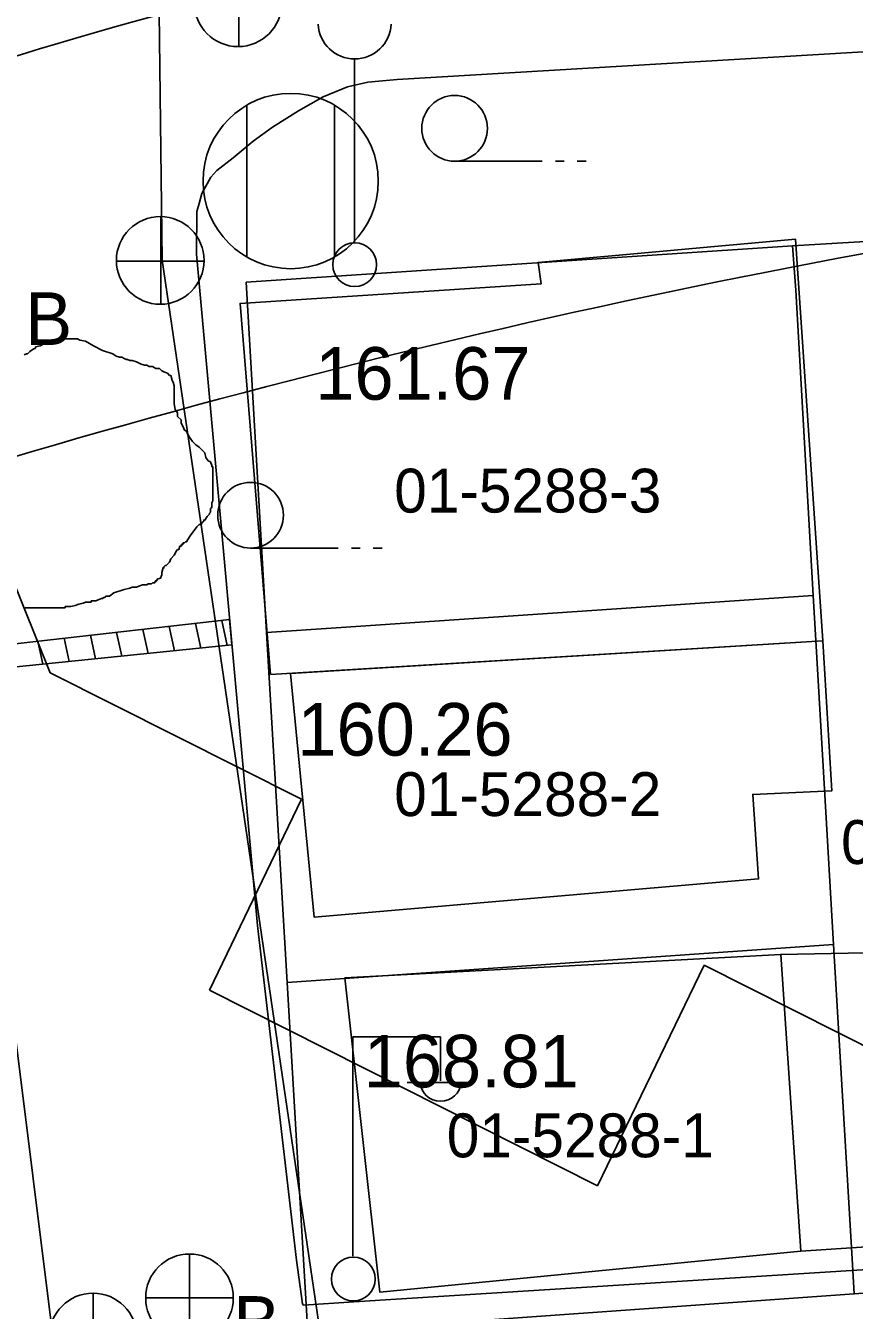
# Model space of a CAD drawing. Extents: x 419101 to 420177, y 4451541 to 4452254.
# Drawn here: x 419848.32 to 419867.23, y 4451802.86 to 4451832.16 of the extents above; entities that cross this region are included whole.
import ezdxf

# ---------------------------------------------------------------- set-up
doc = ezdxf.new("R2010")
doc.units = 0
for name, color, linetype in [('2_KADASTRO', 7, 'Continuous'), ('3_HALİHAZIR', 7, 'Continuous'), ('Level 10', 7, 'Continuous'), ('Level 3', 7, 'Continuous'), ('Level 60', 7, 'Continuous'), ('Level 62', 7, 'Continuous')]:
    doc.layers.add(name, color=color, linetype=linetype)

msp = doc.modelspace()

# ---------------------------------------------------------------- linework, layer by layer
at = {"layer": '2_KADASTRO'}
for points in [[(419865.822, 4451827.135), (419867.101, 4451827.211), (419873.808, 4451827.609), (419874.764, 4451812.159), (419875.281, 4451803.805), (419867.231, 4451803.234), (419867.184, 4451804.033), (419866.761, 4451811.2), (419866.552, 4451814.744), (419866.352, 4451818.137), (419866.293, 4451819.166), (419865.895, 4451826.126)], [(419853.349, 4451826.308), (419865.822, 4451827.135), (419865.895, 4451826.126), (419866.293, 4451819.166), (419855.404, 4451818.429), (419853.82, 4451818.321)], [(419853.82, 4451818.321), (419855.404, 4451818.429), (419866.293, 4451819.166), (419866.352, 4451818.137), (419866.552, 4451814.744), (419866.761, 4451811.2), (419864.238, 4451811.025), (419856.147, 4451810.464), (419854.291, 4451810.335)], [(419854.291, 4451810.335), (419856.147, 4451810.464), (419864.238, 4451811.025), (419866.761, 4451811.2), (419867.184, 4451804.033), (419867.231, 4451803.234), (419854.762, 4451802.349)]]:
    msp.add_lwpolyline(points, close=True, dxfattribs=at)
at = {"layer": '3_HALİHAZIR'}
for p, q in [((419853.184, 4451831.675), (419853.184, 4451833.675)), ((419855.828, 4451827.209), (419855.828, 4451831.402)), ((419853.368, 4451826.886), (419853.368, 4451830.346)), ((419855.368, 4451826.886), (419855.368, 4451830.346)), ((419858.11, 4451829.068), (419860.11, 4451829.068)), ((419860.41, 4451829.068), (419860.61, 4451829.068)), ((419860.91, 4451829.068), (419861.11, 4451829.068)), ((419851.406, 4451825.798), (419851.406, 4451827.798)), ((419850.386, 4451826.788), (419852.386, 4451826.788)), ((419853.453, 4451820.244), (419855.453, 4451820.244)), ((419855.753, 4451820.244), (419855.953, 4451820.244)), ((419856.253, 4451820.244), (419856.453, 4451820.244)), ((419850.995, 4451818.391), (419851.117, 4451817.841)), ((419851.594, 4451818.459), (419851.718, 4451817.903)), ((419852.194, 4451818.527), (419852.319, 4451817.965)), ((419852.794, 4451818.595), (419852.92, 4451818.026)), ((419848.597, 4451818.119), (419848.713, 4451817.595)), ((419849.196, 4451818.187), (419849.314, 4451817.657)), ((419849.796, 4451818.255), (419849.915, 4451817.718)), ((419850.395, 4451818.323), (419850.516, 4451817.78)), ((419855.79, 4451804.097), (419855.79, 4451809.097)), ((419855.79, 4451809.097), (419857.79, 4451809.097)), ((419857.79, 4451808.097), (419857.79, 4451809.097)), ((419857.03, 4451808.057), (419858.53, 4451808.057)), ((419852.059, 4451804.144), (419852.059, 4451802.144)), ((419849.857, 4451803.25), (419849.857, 4451801.25)), ((419851.059, 4451803.144), (419853.059, 4451803.144))]:
    msp.add_line(p, q, dxfattribs=at)
for points in [[(419883.249, 4451832.652), (419868.981, 4451831.651), (419856.797, 4451830.93), (419856.127, 4451830.87), (419855.662, 4451830.764), (419855.112, 4451830.539), (419854.549, 4451830.22), (419853.951, 4451829.847), (419853.514, 4451829.523), (419853.056, 4451829.143), (419852.682, 4451828.854), (419852.544, 4451828.705), (419852.34, 4451828.329), (419852.279, 4451828.101), (419852.229, 4451827.92), (419852.216, 4451826.947)], [(419852.216, 4451826.947), (419853.61, 4451811.636), (419854.5, 4451804)], [(419847.624, 4451812.746), (419850.189, 4451792.286), (419852.538, 4451774.604), (419854.108, 4451764.505)], [(419884.682, 4451804.733), (419875.752, 4451804.31), (419855.808, 4451803.057), (419854.663, 4451802.975), (419854.663, 4451802.975), (419854.636, 4451803.009), (419854.5, 4451804)]]:
    msp.add_lwpolyline(points, dxfattribs=at)
for points in [[(419853.907, 4451817.359), (419853.212, 4451825.827), (419860.085, 4451826.269), (419860.016, 4451826.756), (419865.888, 4451827.293), (419866.516, 4451818.127)], [(419846.911, 4451817.411), (419846.799, 4451817.915), (419852.975, 4451818.615), (419853.027, 4451818.037)], [(419866.516, 4451818.127), (419866.723, 4451814.71), (419864.915, 4451814.625), (419865.049, 4451812.701), (419854.907, 4451811.825), (419854.362, 4451817.387)], [(419866.012, 4451804.212), (419868.664, 4451804.382), (419868.238, 4451811.029), (419865.553, 4451810.977), (419855.604, 4451810.44), (419856.402, 4451803.274)], [(419866.012, 4451804.212), (419865.553, 4451810.977), (419868.238, 4451811.029), (419868.664, 4451804.382)]]:
    msp.add_lwpolyline(points, close=True, dxfattribs=at)
for centre, radius in [((419853.168, 4451832.683), 1), ((419854.368, 4451828.616), 2), ((419858.11, 4451829.818), 0.75), ((419851.391, 4451826.806), 1), ((419855.828, 4451826.709), 0.5), ((419853.453, 4451820.994), 0.75), ((419852.059, 4451803.144), 1), ((419855.8, 4451803.573), 0.5), ((419849.857, 4451802.25), 1)]:
    msp.add_circle(centre, radius, dxfattribs=at)
for centre, radius, start, end in [((419855.828, 4451832.239), 0.837, 183.298, 356.9072), ((419857.79, 4451808.101), 0.474, 184.8384, 355.1464)]:
    msp.add_arc(centre, radius, start, end, dxfattribs=at)
at = {"layer": 'Level 10'}
msp.add_lwpolyline([(419958.201, 4451879.006), (419966.53, 4451769.671), (419931.06, 4451766.859), (419938.096, 4451697.79), (419879.097, 4451703.767), (419870.357, 4451698.446), (419851.433, 4451826.814), (419850.731, 4451885.176)], dxfattribs=at)
at = {"layer": 'Level 3'}
for points in [[(419848.285, 4451824.65), (419848.337, 4451824.676), (419848.363, 4451824.676), (419848.414, 4451824.728), (419848.492, 4451824.78), (419848.544, 4451824.806), (419848.544, 4451824.832), (419848.648, 4451824.858)], [(419848.648, 4451824.858), (419848.752, 4451824.91), (419848.855, 4451824.936), (419848.855, 4451824.962), (419848.881, 4451824.962), (419848.907, 4451824.962), (419848.985, 4451824.962), (419849.115, 4451825.014), (419849.219, 4451825.014), (419849.296, 4451825.014), (419849.348, 4451825.014), (419849.426, 4451825.014), (419849.478, 4451825.014), (419849.504, 4451825.014), (419849.556, 4451824.988), (419849.686, 4451824.962), (419849.867, 4451824.858), (419850.075, 4451824.754), (419850.308, 4451824.676), (419850.386, 4451824.624), (419850.464, 4451824.598), (419850.516, 4451824.598), (419850.568, 4451824.572), (419850.619, 4451824.546), (419850.645, 4451824.546), (419850.697, 4451824.52), (419850.749, 4451824.52), (419850.853, 4451824.494), (419850.957, 4451824.442), (419851.034, 4451824.416), (419851.086, 4451824.416), (419851.138, 4451824.39), (419851.19, 4451824.39), (419851.216, 4451824.39), (419851.294, 4451824.339), (419851.372, 4451824.339), (419851.424, 4451824.287), (419851.475, 4451824.261), (419851.553, 4451824.235), (419851.605, 4451824.183), (419851.631, 4451824.183), (419851.657, 4451824.105), (419851.657, 4451824.079), (419851.683, 4451824.027), (419851.709, 4451823.949), (419851.709, 4451823.923), (419851.709, 4451823.845), (419851.709, 4451823.793), (419851.709, 4451823.715), (419851.709, 4451823.689), (419851.709, 4451823.611), (419851.709, 4451823.534), (419851.735, 4451823.404), (419851.787, 4451823.326), (419851.787, 4451823.248), (419851.865, 4451823.17), (419851.865, 4451823.092), (419851.916, 4451823.014), (419851.942, 4451822.936), (419851.994, 4451822.91), (419852.02, 4451822.832), (419852.072, 4451822.754), (419852.124, 4451822.677), (419852.202, 4451822.599), (419852.28, 4451822.547), (419852.331, 4451822.495), (419852.357, 4451822.469), (419852.409, 4451822.417), (419852.435, 4451822.313), (419852.487, 4451822.235), (419852.539, 4451822.209), (419852.565, 4451822.131), (419852.565, 4451822.105), (419852.591, 4451822.105), (419852.591, 4451822.079), (419852.591, 4451822.053), (419852.591, 4451822.001), (419852.591, 4451821.898), (419852.591, 4451821.846), (419852.591, 4451821.768), (419852.591, 4451821.69), (419852.591, 4451821.612), (419852.591, 4451821.534), (419852.591, 4451821.456), (419852.591, 4451821.404), (419852.591, 4451821.326), (419852.565, 4451821.274), (419852.565, 4451821.17), (419852.539, 4451821.144), (419852.539, 4451821.067), (419852.513, 4451821.041), (419852.513, 4451821.015), (419852.461, 4451820.963), (419852.409, 4451820.885), (419852.383, 4451820.885), (419852.383, 4451820.859), (419852.357, 4451820.833), (419852.331, 4451820.807), (419852.331, 4451820.781), (419852.306, 4451820.781), (419852.28, 4451820.781)], [(419852.28, 4451820.781), (419852.228, 4451820.729), (419852.072, 4451820.521), (419852.02, 4451820.443), (419851.994, 4451820.391), (419851.968, 4451820.391), (419851.942, 4451820.365), (419851.916, 4451820.365), (419851.916, 4451820.339), (419851.89, 4451820.339), (419851.89, 4451820.313), (419851.865, 4451820.313), (419851.865, 4451820.287), (419851.839, 4451820.287), (419851.813, 4451820.21), (419851.787, 4451820.21), (419851.761, 4451820.184), (419851.709, 4451820.08), (419851.631, 4451820.002), (419851.605, 4451819.924), (419851.527, 4451819.846), (419851.501, 4451819.846), (419851.475, 4451819.82), (419851.475, 4451819.794), (419851.449, 4451819.794), (419851.449, 4451819.768), (419851.424, 4451819.69), (419851.424, 4451819.638), (419851.398, 4451819.56), (419851.32, 4451819.534), (419851.32, 4451819.508), (419851.294, 4451819.508), (419851.294, 4451819.482), (419851.268, 4451819.482), (419851.268, 4451819.456), (419851.242, 4451819.456), (419851.216, 4451819.456), (419851.19, 4451819.431), (419851.164, 4451819.431), (419851.138, 4451819.431), (419851.112, 4451819.431), (419851.086, 4451819.405), (419851.06, 4451819.405), (419851.034, 4451819.405), (419851.008, 4451819.405), (419850.983, 4451819.405), (419850.905, 4451819.379), (419850.853, 4451819.353), (419850.775, 4451819.353), (419850.749, 4451819.353), (419850.697, 4451819.327), (419850.568, 4451819.301), (419850.334, 4451819.223), (419850.23, 4451819.145), (419850.152, 4451819.145), (419850.127, 4451819.119), (419850.101, 4451819.119), (419850.075, 4451819.093), (419850.049, 4451819.093), (419849.971, 4451819.067), (419849.919, 4451819.041), (419849.893, 4451819.041), (419849.867, 4451819.041), (419849.841, 4451819.041), (419849.815, 4451819.041), (419849.815, 4451819.015), (419849.789, 4451819.015), (419849.763, 4451819.015), (419849.686, 4451819.015), (419849.634, 4451818.989), (419849.53, 4451818.963), (419849.452, 4451818.937), (419849.348, 4451818.911), (419849.296, 4451818.911), (419849.27, 4451818.911), (419849.245, 4451818.911), (419849.219, 4451818.911), (419849.219, 4451818.885), (419849.193, 4451818.885), (419849.167, 4451818.885), (419849.141, 4451818.885), (419849.115, 4451818.885), (419849.089, 4451818.885), (419849.063, 4451818.885), (419849.037, 4451818.885), (419849.011, 4451818.885), (419848.985, 4451818.885), (419848.907, 4451818.885), (419848.855, 4451818.885), (419848.778, 4451818.885), (419848.726, 4451818.885), (419848.7, 4451818.885), (419848.674, 4451818.885), (419848.622, 4451818.885), (419848.544, 4451818.885), (419848.518, 4451818.885), (419848.466, 4451818.885), (419848.44, 4451818.885), (419848.388, 4451818.885), (419848.363, 4451818.885), (419848.337, 4451818.885)], [(419848.337, 4451818.885), (419848.311, 4451818.885)]]:
    msp.add_lwpolyline(points, dxfattribs=at)
at = {"layer": 'Level 60'}
msp.add_arc((419876.549, 4451739.049), 96.699, 94.2053, 110.62966, dxfattribs=at)
at = {"layer": 'Level 62'}
for p, q in [((419848.882, 4451817.403), (419847.007, 4451822.026)), ((419848.882, 4451817.403), (419847.007, 4451822.026)), ((419848.882, 4451817.403), (419847.007, 4451822.026)), ((419848.882, 4451817.403), (419854.614, 4451814.515)), ((419848.882, 4451817.403), (419854.614, 4451814.515)), ((419848.882, 4451817.403), (419854.614, 4451814.515)), ((419852.513, 4451810.163), (419854.614, 4451814.515)), ((419852.513, 4451810.163), (419854.614, 4451814.515)), ((419852.513, 4451810.163), (419854.614, 4451814.515)), ((419861.375, 4451805.699), (419863.805, 4451810.731)), ((419861.375, 4451805.699), (419863.805, 4451810.731)), ((419861.375, 4451805.699), (419863.805, 4451810.731)), ((419863.805, 4451810.731), (419868.146, 4451808.545)), ((419863.805, 4451810.731), (419868.146, 4451808.545)), ((419863.805, 4451810.731), (419868.146, 4451808.545)), ((419852.513, 4451810.163), (419861.375, 4451805.699)), ((419852.513, 4451810.163), (419861.375, 4451805.699)), ((419852.513, 4451810.163), (419861.375, 4451805.699))]:
    msp.add_line(p, q, dxfattribs=at)
for centre, radius, start, end in [((419838.814, 4451843.978), 13, 290.1603, 31.867), ((419902.659, 4451636.882), 193.317, 95.90854, 106.44394)]:
    msp.add_arc(centre, radius, start, end, dxfattribs=at)

# ---------------------------------------------------------------- texts
at = {"layer": '2_KADASTRO'}
for s, p in [('01-5288-3', (419856.731, 4451821.055)), ('01-5288-2', (419856.731, 4451814.133)), ('01-5288-4', (419866.931, 4451813.04)), ('01-5288-1', (419857.93, 4451806.35))]:
    msp.add_text(s, height=1, dxfattribs=at).set_placement(p)
at = {"layer": '3_HALİHAZIR'}
for s, p in [('B', (419848.31, 4451824.878)), ('161.67', (419854.932, 4451823.628)), ('160.26', (419854.523, 4451815.511)), ('168.81', (419856.037, 4451807.943)), ('B', (419853.059, 4451801.983))]:
    msp.add_text(s, height=1.2, dxfattribs=at).set_placement(p)

doc.saveas('drawing.dxf')
